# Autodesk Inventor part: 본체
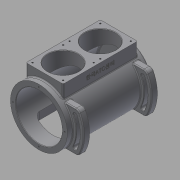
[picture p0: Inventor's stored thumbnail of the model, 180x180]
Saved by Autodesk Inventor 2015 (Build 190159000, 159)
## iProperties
Created: 2016-11
Part Number: 본체
Material: 알루미늄 6061
Document SubType Name: Modeling
Designer: mduedu
Density: 2.71 g/cm^3
Appearance: 기본값
Author: mduedu
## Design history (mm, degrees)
sketch "스케치1"
  geometry: C1 r 65 at (0, 0); 1 further point
  constraints: 1 centre point, 1 coincident
  dimensions: "d119" = 130 diameter of C1
extrude "돌출1" new body sketch "스케치1" distance "d3" = 98; taper "d4" = 0 deg; dims "d132" = 97, "d133" = 0
feature "쉘1" dims "d120" = 12, "d134" = 8
node "작업 평면2"
sketch "스케치13"
  geometry: L1 (42.5, 85)-(-42.5, 85); L2 (-42.5, 85)-(-42.5, -85); L3 (-42.5, -85)-(42.5, -85); L4 (42.5, -85)-(42.5, 85); 2 further points
  constraints: 8 end point, 2 parallel, 1 horizontal, 1 midpoint, 1 perpendicular, 1 vertical alignment
  dimensions: "d122" = 170 distance of L1.end L2.end; "d124" = 85 distance of L2.end L3.end; "d125" = 85 distance from line of point (0, 0) L1 (= 0.5 x d122)
extrude "돌출11" join sketch "스케치13" stored distance "d126" = 10; taper "d127" = 0 deg
sketch "스케치14"
  geometry: L1 (65, 97)-(-65, 97) reference; C1 r 35 at (0, 42.5); 1 further point
  constraints: 1 centre point, 1 vertical alignment
  dimensions: "d128" = 70 diameter of C1; "d129" = 54.5 distance from line of C1.centre L1
extrude "돌출12" cut sketch "스케치14" stored distance "d130" = 10; taper "d131" = 0 deg
sketch "스케치15"
  geometry: C1 r 53 at (0, 0) reference; 1 further point
extrude "돌출13" cut sketch "스케치15" stored distance "d135" = 10; taper "d136" = 0 deg
chamfer "모따기1" distance "d54" = 1; stored, may be unused: second distance "d55" = 2, angle "d56" = 45 deg
sketch "스케치8"
  geometry: C1 r 23 at (0, 0); C2 r 65 at (0, 0) reference; 1 further point
  constraints: 1 centre point, 1 concentric
  dimensions: "d57" = 46 diameter of C1
extrude "돌출8" join sketch "스케치8" distance "d58" = 14; taper "d59" = 0 deg
hole "구멍3" diameter "d62" = 24; stored, may be unused: countersink angle "d66" = 90 deg, drill point angle "d68" = 0 deg; dims "d63" = 6, "d64" = 28, "d65" = 8, "d67" = 14, "d169" = 10, "d170" = 10
fillet "모깎기11" dims "d69" = 3
fillet "모깎기12" dims "d70" = 3
fillet "모깎기13" dims "d71" = 0.3
chamfer "모따기2" distance "d72" = 1; stored, may be unused: second distance "d73" = 2, angle "d74" = 45 deg
node "작업 평면3"
sketch "스케치16"
  geometry: L1 (-42.5, -80)-(47.5, -80); L2 (-42.5, -80)-(21.14, -16.36); L3 (-42.5, -80)-(21.14, -143.64); L4 (3.462, -34.038)-(34.879, -34.038); L5 (3.462, -125.962)-(34.879, -125.962); A1 r 65 centre (-42.5, -80) between (3.462, -34.038) and (3.462, -125.962) reference; A2 r 90 centre (-42.5, -80) between (34.879, -125.962) and (34.879, -34.038); A3 r 90 centre (-42.5, -80) between (34.879, -34.038) and (34.879, -125.962); A4 r 65 centre (-42.5, -80) between (3.462, -125.962) and (3.462, -34.038); 1 further point
  constraints: 11 point on circle, 10 end point, 3 centre point, 2 parallel, 2 point on line, 1 coincident, 1 horizontal
  dimensions: "d140" = 45 deg angle of L3 L1; "d141" = 45 deg angle of L2 L1; "d142" = 25 radial gap between concentric circles of A1 A2
extrude "돌출14" join sketch "스케치16" distance "d143" = 15; taper "d144" = 0 deg
sketch "스케치17"
  geometry: L1 (-42.5, -80)-(34.414, -80); L2 (-42.5, -80)-(27.208, -47.495); L3 (-42.5, -80)-(27.208, -112.505); L4 (34.879, -34.038)-(3.462, -34.038) reference; L5 (3.462, -125.962)-(34.879, -125.962) reference; A1 r 65 centre (-42.5, -80) between (3.462, -34.038) and (3.462, -125.962) reference; A2 r 76.914 centre (-42.5, -80) between (19.17, -125.962) and (19.17, -34.038); A3 r 4 centre (27.208, -47.495) between (23.582, -49.185) and (30.833, -45.804); A4 r 4 centre (27.208, -112.505) between (30.833, -114.196) and (23.582, -110.815); A5 r 80.914 centre (-42.5, -80) between (30.833, -114.196) and (30.833, -45.804); A6 r 72.914 centre (-42.5, -80) between (23.582, -110.815) and (23.582, -49.185); 1 further point
  constraints: 13 point on circle, 6 end point, 5 centre point, 5 coincident, 3 midpoint, 2 point on line, 1 equal radius, 1 horizontal
  dimensions: "d145" = 25 deg angle of L1 L3; "d146" = 25 deg angle of L2 L1; "d147" = 8 diameter of A3
extrude "돌출15" cut sketch "스케치17" stored distance "d150" = 15; taper "d151" = 0 deg
fillet "모깎기17" dims "d152" = 10
fillet "모깎기18" dims "d153" = 2
fillet "모깎기19" dims "d154" = 2
chamfer "모따기4" distance "d155" = 1; stored, may be unused: second distance "d156" = 2, angle "d157" = 45 deg
fillet "모깎기20" dims "d159" = 3
fillet "모깎기21" dims "d160" = 3
fillet "모깎기22" dims "d161" = 3
node "작업 평면4"
sketch "스케치18"
  geometry: L1 (-42.5, 65)-(42.5, 65); L2 (42.5, 65)-(42.5, -65); L3 (42.5, -65)-(-42.5, -65); L4 (-42.5, -65)-(-42.5, 65); 2 further points
  constraints: 8 end point, 2 parallel, 1 horizontal, 1 midpoint, 1 perpendicular, 1 vertical alignment
  dimensions: "d162" = 130 distance of L1.end L2.end; "d164" = 85 distance of L2.end L3.end; "d165" = 65 distance from line of point (0, 0) L1 (= 0.5 x d162)
extrude "돌출16" cut sketch "스케치18" stored distance "d166" = 15; taper "d167" = 0 deg
fillet "모깎기23" dims "d168" = 10
fillet "모깎기24" dims "d173" = 3
sketch "스케치19"
  geometry: 4 further points
  constraints: 4 other
hole "구멍6" sketch "스케치19" at (0, -59), (59, 0), (-59, 0), (0, 59) diameter "d174" = 3.242; stored, may be unused: countersink angle "d178" = 90 deg, drill point angle "d180" = 120 deg; dims "d175" = 7, "d176" = 4, "d177" = 2, "d179" = 9
sketch "스케치20"
  geometry: L1 (35, -77.5)-(-35, -77.5); L2 (-35, -77.5)-(-35, -7.5); L3 (-35, -7.5)-(35, -7.5); L4 (35, -7.5)-(35, -77.5); L5 (35, -77.5)-(-35, -7.5); L6 (-35, -77.5)-(35, -7.5); C1 r 36 at (0, -42.5) reference; 5 further points
  constraints: 12 end point, 4 coincident, 2 midpoint, 2 parallel, 1 horizontal, 1 perpendicular
  dimensions: "d181" = 70 distance of L2.end L3.end; "d182" = 70 distance of L1.end L2.end
hole "구멍7" sketch "스케치20" at (-35, -77.5), (-35, -7.5), (35, -7.5), (35, -77.5) diameter "d183" = 3.242; stored, may be unused: countersink angle "d187" = 90 deg, drill point angle "d189" = 118 deg; dims "d184" = 7, "d185" = 4, "d186" = 2, "d188" = 9
sketch "스케치21"
  geometry: L1 (164, 0)-(0, 0) reference; L2 (-3, 0)-(-3, -24.649) reference; 3 further points
  constraints: 1 midpoint, 1 vertical alignment, 1 other
  dimensions: "d190" = 15 distance from line of point (82, -15) L1; "d191" = 85 distance from line of point (82, 0) L2 (derived)
feature "엠보싱2" sketch "스케치21" dims "d3" = 98, "d4" = 0, "d119" = 130, "d132" = 97, "d133" = 0, "d192" = 0.5, "d193" = 0
node "솔리드1"
mirror "대칭5"
mirror "대칭6"
mirror "대칭7"
